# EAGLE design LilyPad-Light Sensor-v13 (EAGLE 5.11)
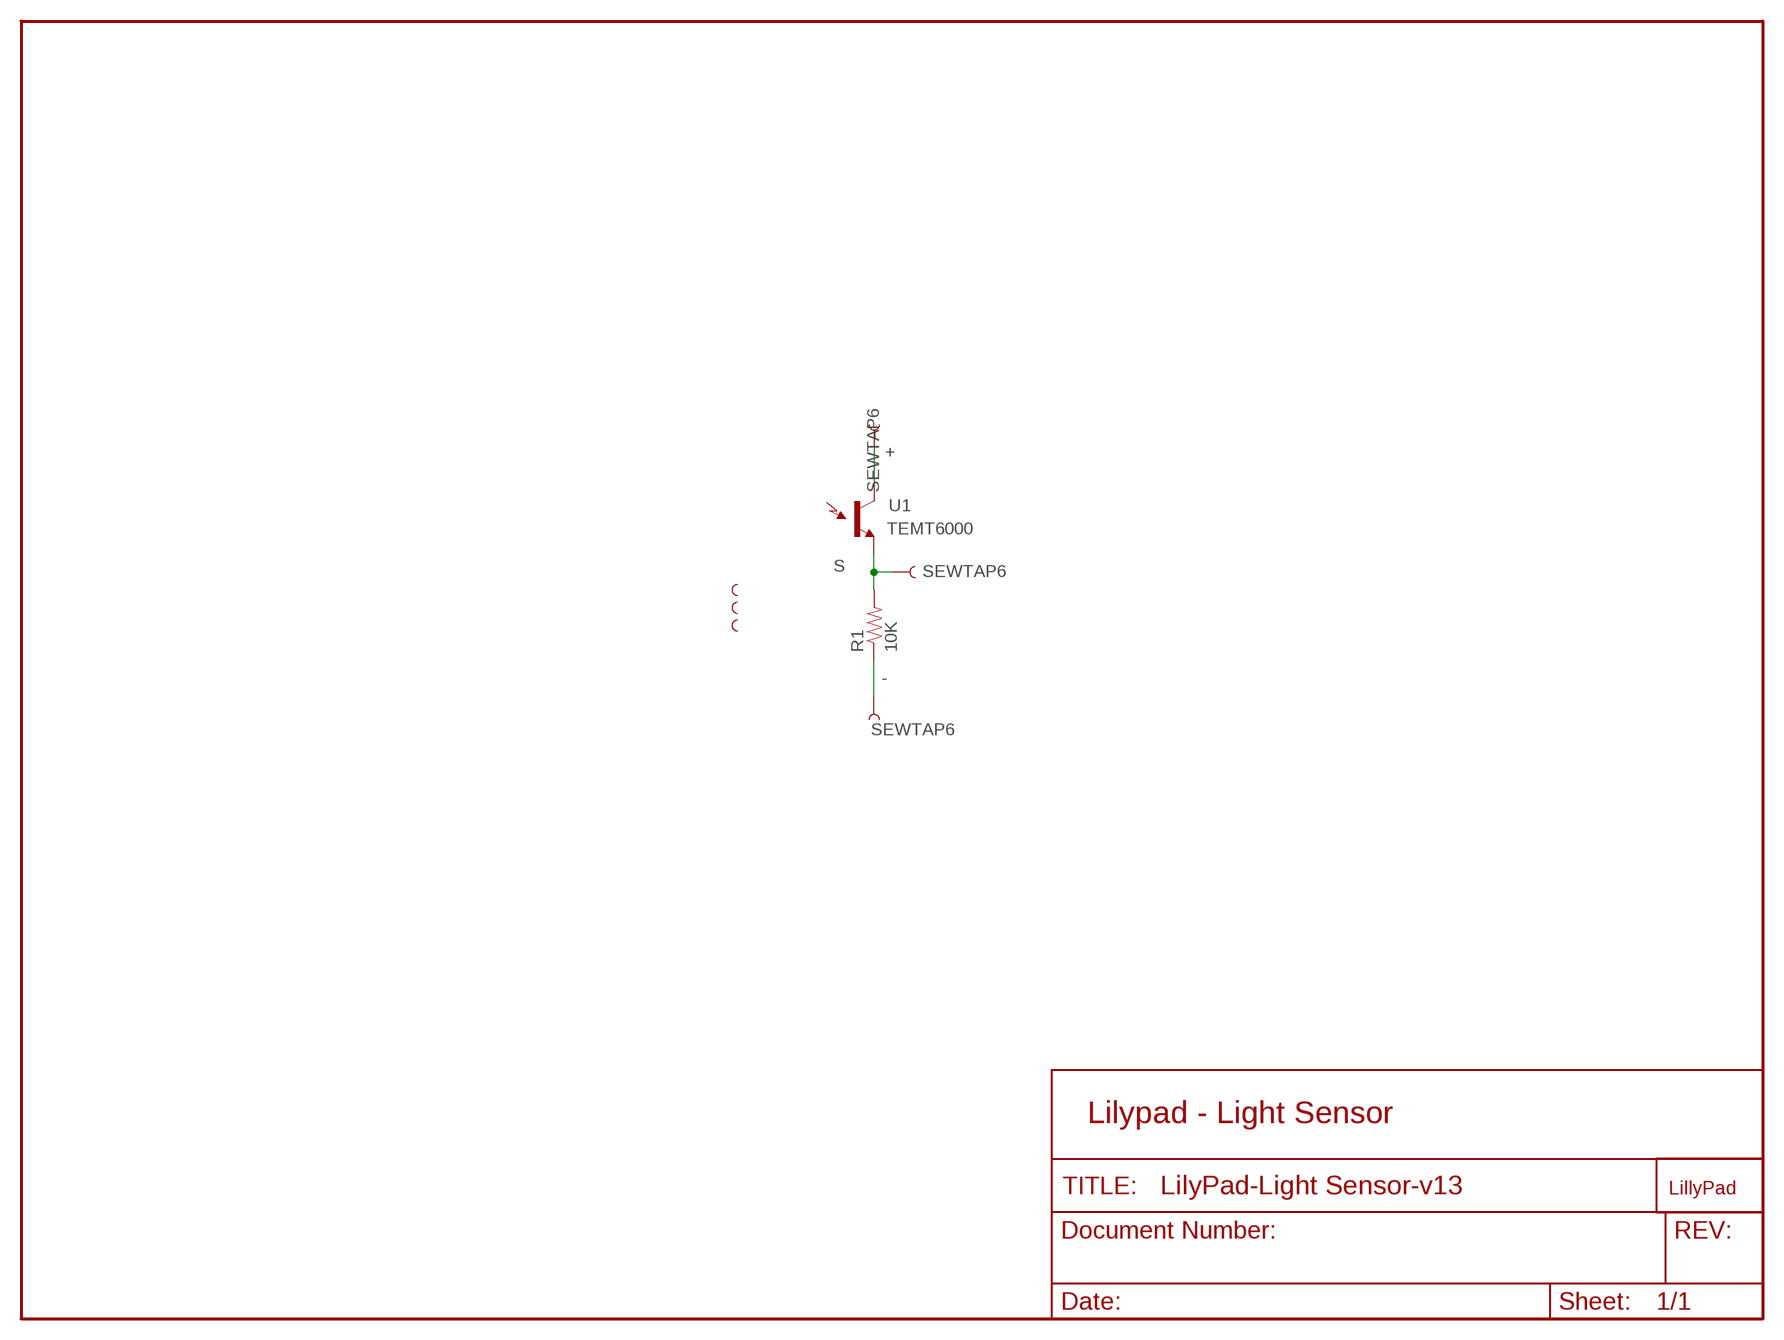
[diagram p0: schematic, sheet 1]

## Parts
LIGHT1  SEWTAP-NOHOLE2  [PETAL-NOHOLE-2SIDE]
LIGHT2  SEWTAP-NOHOLE2  [PETAL-NOHOLE-2SIDE]
LIGHT3  SEWTAP-NOHOLE2  [PETAL-NOHOLE-2SIDE]
LIGHT+  SEWTAP6  [PETAL-SMALL-2SIDE]
LIGHT-  SEWTAP6  [PETAL-SMALL-2SIDE]
LIGHTS  SEWTAP6  [PETAL-SMALL-2SIDE]
R1  10K  RESISTOR0402  [C0402]
U1  TEMT6000  [TEMT6000-SEN]
U$2  LOGO-LPLP  [LOGO-LILYPAD]

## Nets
+: LIGHT+.1 U1.COLLECTOR(C1)
-: LIGHT-.1 R1.1
S: LIGHTS.1 R1.2 U1.EMITTER(E1)

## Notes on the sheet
- Lilypad - Light Sensor

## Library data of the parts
LIGHT1-LIGHT3 = LilyPad-Wearables:SEWTAP-NOHOLE
LIGHT+ LIGHT- LIGHTS = LilyPad-Wearables:SEWTAP
R1 = SparkFun:RESISTOR: Resistor
U1 = SparkFun:TEMT6000: Ambient Light Sensor
U$2 = LilyPad-Wearables:LOGO-LP

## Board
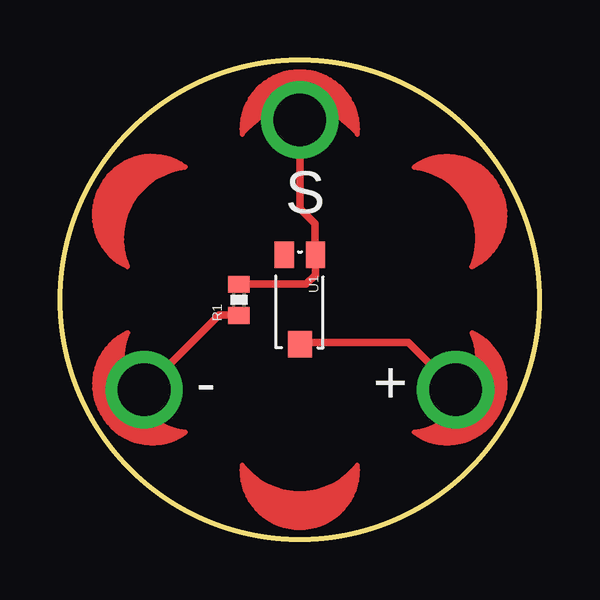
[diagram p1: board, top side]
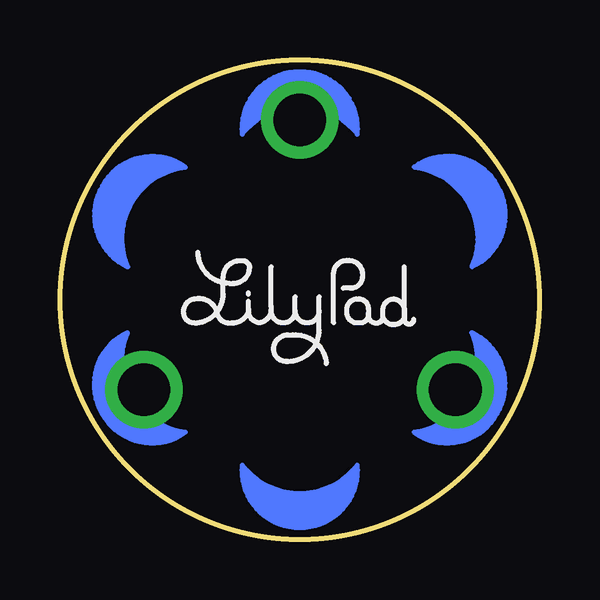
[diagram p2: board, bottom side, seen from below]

Size 20 x 20 mm. Coordinates in mm from the lower left corner, seen from the top.
Outline: circle at 10,10 radius 10
Copper layers (1*16): Top 0.035mm / dielectric 1.5mm / Bottom 0.035mm
Design rules "SparkFun": minimum track width 8mil, minimum drill 20mil, track to track 8mil, track to pad 8mil, pad to pad 8mil, via to via 8mil, smd to smd 8mil, copper to edge 8mil, drill to drill 8mil, minimum pad ring 12mil, minimum via ring 10mil, stop-mask expansion 4mil, vias tented up to drill 20mil, thermal gap 10mil

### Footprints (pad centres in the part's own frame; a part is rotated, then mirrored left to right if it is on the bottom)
PETAL-SMALL-2SIDE = drill 2.2 round: 1 0,0
0402-RES = smd 0.7 x 0.9: 1 -0.65,0; 2 0.65,0
TEMT6000-SEN = smd 1.1 x 0.8: BASE -1.87,-0.65; EMITTER -1.87,0.65 | smd 1.1 x 1: COLLECTOR 1.86,0.01

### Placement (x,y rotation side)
LIGHT1  3.5,13.76 240 top
LIGHT2  10,2.51 0 top
LIGHT3  16.49,13.75 120 top
LIGHT+  16.5,6.25 60 top
LIGHT-  3.51,6.25 300 top
LIGHTS  10,17.5 180 top
R1  10K  [0402-RES]  7.46,10 90 top
U1  10,10 270 top
U$2  10,10 0 bottom

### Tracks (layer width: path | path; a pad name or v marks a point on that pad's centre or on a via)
+
  Top 0.305: U1.COLLECTOR 10.09,8.22 14.53,8.22 LIGHT+.1
-
  Top 0.305: R1.1 7.46,9.37 6.62,9.37 LIGHT-.1
S
  Top 0.305: LIGHTS.1 10,13.81 10.63,13.18 10.63,11.86 | 10.63,11.86 10.63,11.78 | 10.63,11.86 U1.EMITTER 10.65,11.03 10.27,10.65 R1.2

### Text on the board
tPlace: S | - | +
